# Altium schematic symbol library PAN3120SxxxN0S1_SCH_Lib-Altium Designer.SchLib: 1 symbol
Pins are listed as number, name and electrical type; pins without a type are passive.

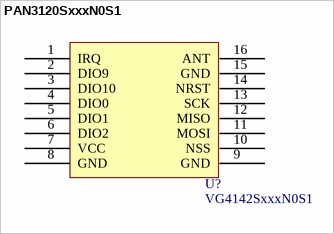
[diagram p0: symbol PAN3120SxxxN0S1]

## PAN3120SxxxN0S1
designator U?, comment VG4142SxxxN0S1
footprint G238xNS1
footprint G238xNS1_TO
pins: 1 IRQ, 2 DIO9, 3 DIO10, 4 DIO0, 5 DIO1, 6 DIO2, 7 VCC, 8 GND, 9 GND, 10 NSS, 11 MOSI, 12 MISO, 13 SCK, 14 NRST, 15 GND, 16 ANT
